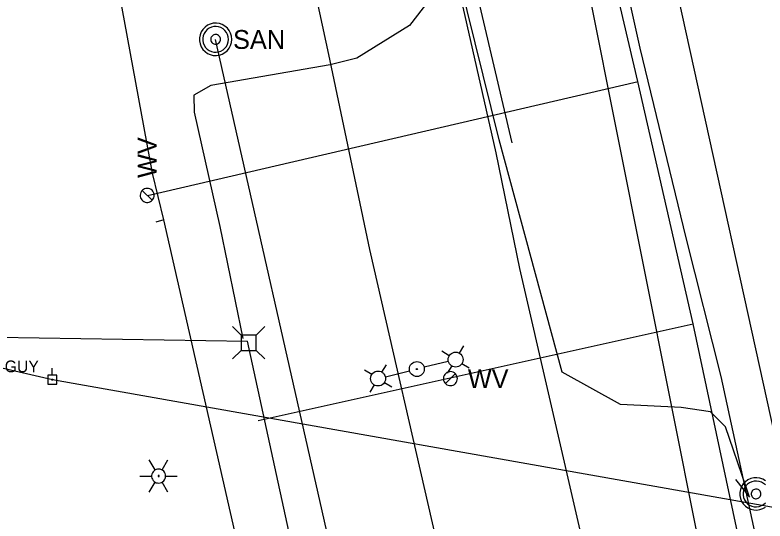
# Model space of a CAD drawing. Extents: x 596028 to 606371, y 330010 to 403088.
# Drawn here: x 604712 to 604864.8, y 339167.3 to 339270.5 of the extents above; entities that cross this region are included whole.
import ezdxf

# ---------------------------------------------------------------- set-up
doc = ezdxf.new("R2010")
doc.units = 0
for name, color, linetype in [('E_LTG', 7, 'Continuous'), ('E_UTL_E_UG', 7, 'Continuous'), ('E_UTL_EGuyWire', 7, 'Continuous'), ('E_UTL_EPowerPole', 7, 'Continuous'), ('E_UTL_FO_UG', 7, 'Continuous'), ('E_UTL_G_UG', 7, 'Continuous'), ('E_UTL_Overhead', 7, 'Continuous'), ('E_UTL_SAN_MH', 7, 'Continuous'), ('E_UTL_SAN_UG', 7, 'Continuous'), ('E_UTL_SAN_UG_MMSD', 7, 'Continuous'), ('E_UTL_T', 7, 'Continuous'), ('E_UTL_T_MH', 7, 'Continuous'), ('E_UTL_T_UG', 7, 'Continuous'), ('E_UTL_W', 7, 'Continuous'), ('E_UTL_W_UG', 7, 'Continuous')]:
    doc.layers.add(name, color=color, linetype=linetype)

# ---------------------------------------------------------------- blocks, each defined once
blk = doc.blocks.new('PPOL')
at = {"layer": 'E_UTL_EPowerPole'}
blk.add_line((-0.2, 13.7), (-0.2, 35.3), dxfattribs=at)
blk.add_lwpolyline([(-13.9, -13.7), (13.5, -13.7), (13.5, 13.7), (-13.9, 13.7)], close=True, dxfattribs=at)
blk.add_circle((0, 0), 1.77, dxfattribs=at)
blk = doc.blocks.new('GUY')
at = {"layer": 'E_UTL_EGuyWire'}
for radius in [12.2, 1.52]:
    blk.add_circle((0, 0), radius, dxfattribs=at)
blk.add_text('GUY', height=36.58, dxfattribs=at).set_placement((30.5, -18.3))

msp = doc.modelspace()

# ---------------------------------------------------------------- linework, layer by layer
at = {"layer": 'E_LTG'}
for p, q in [((604800.51, 339200.96), (604799.01, 339201.87)), ((604802.58, 339201.47), (604803.5, 339202.97)), ((604786.79, 339197.61), (604787.71, 339199.12)), ((604800.29, 339199.81), (604795.41, 339198.62)), ((604801.02, 339198.89), (604800.1, 339197.38)), ((604803.09, 339199.39), (604804.59, 339198.48)), ((604784.72, 339197.11), (604783.22, 339198.02)), ((604787.51, 339196.69), (604792.4, 339197.88)), ((604785.23, 339195.03), (604784.31, 339193.53)), ((604787.3, 339195.54), (604788.8, 339194.63))]:
    msp.add_line(p, q, dxfattribs=at)
for points in [[(604740.57, 339177.67), (604739.38, 339179.73)], [(604742, 339177.67), (604743.19, 339179.73)], [(604742.71, 339176.43), (604742.69, 339176.7), (604742.61, 339176.97), (604742.49, 339177.21), (604742.32, 339177.42), (604742.11, 339177.6), (604741.88, 339177.73), (604741.62, 339177.82), (604741.35, 339177.86), (604741.08, 339177.85), (604740.82, 339177.78), (604740.57, 339177.67), (604740.35, 339177.51), (604740.16, 339177.32), (604740.01, 339177.09), (604739.91, 339176.84), (604739.86, 339176.57), (604739.86, 339176.3), (604739.91, 339176.03), (604740.01, 339175.78), (604740.16, 339175.55), (604740.35, 339175.35), (604740.57, 339175.2), (604740.82, 339175.08), (604741.08, 339175.02), (604741.35, 339175.01), (604741.62, 339175.05), (604741.88, 339175.13), (604742.11, 339175.27), (604742.32, 339175.45), (604742.49, 339175.66), (604742.61, 339175.9), (604742.69, 339176.16), (604742.71, 339176.43)], [(604742.71, 339176.43), (604742.69, 339176.7), (604742.61, 339176.97), (604742.49, 339177.21), (604742.32, 339177.42), (604742.11, 339177.6), (604741.88, 339177.73), (604741.62, 339177.82), (604741.35, 339177.86), (604741.08, 339177.85), (604740.82, 339177.78), (604740.57, 339177.67), (604740.35, 339177.51), (604740.16, 339177.32), (604740.01, 339177.09), (604739.91, 339176.84), (604739.86, 339176.57), (604739.86, 339176.3), (604739.91, 339176.03), (604740.01, 339175.78), (604740.16, 339175.55), (604740.35, 339175.35), (604740.57, 339175.2), (604740.82, 339175.08), (604741.08, 339175.02), (604741.35, 339175.01), (604741.62, 339175.05), (604741.88, 339175.13), (604742.11, 339175.27), (604742.32, 339175.45), (604742.49, 339175.66), (604742.61, 339175.9), (604742.69, 339176.16), (604742.71, 339176.43)], [(604742.71, 339176.43), (604742.69, 339176.7), (604742.61, 339176.97), (604742.49, 339177.21), (604742.32, 339177.42), (604742.11, 339177.6), (604741.88, 339177.73), (604741.62, 339177.82), (604741.35, 339177.86), (604741.08, 339177.85), (604740.82, 339177.78), (604740.57, 339177.67), (604740.35, 339177.51), (604740.16, 339177.32), (604740.01, 339177.09), (604739.91, 339176.84), (604739.86, 339176.57), (604739.86, 339176.3), (604739.91, 339176.03), (604740.01, 339175.78), (604740.16, 339175.55), (604740.35, 339175.35), (604740.57, 339175.2), (604740.82, 339175.08), (604741.08, 339175.02), (604741.35, 339175.01), (604741.62, 339175.05), (604741.88, 339175.13), (604742.11, 339175.27), (604742.32, 339175.45), (604742.49, 339175.66), (604742.61, 339175.9), (604742.69, 339176.16), (604742.71, 339176.43)], [(604737.47, 339176.43), (604739.86, 339176.43)], [(604741.4, 339176.43), (604741.4, 339176.46), (604741.39, 339176.48), (604741.38, 339176.5), (604741.37, 339176.52), (604741.35, 339176.53), (604741.33, 339176.54), (604741.31, 339176.55), (604741.29, 339176.55), (604741.27, 339176.55), (604741.25, 339176.55), (604741.22, 339176.54), (604741.21, 339176.52), (604741.19, 339176.51), (604741.18, 339176.49), (604741.17, 339176.47), (604741.17, 339176.45), (604741.17, 339176.42), (604741.17, 339176.4), (604741.18, 339176.38), (604741.19, 339176.36), (604741.21, 339176.34), (604741.22, 339176.33), (604741.25, 339176.32), (604741.27, 339176.32), (604741.29, 339176.32), (604741.31, 339176.32), (604741.33, 339176.33), (604741.35, 339176.34), (604741.37, 339176.35), (604741.38, 339176.37), (604741.39, 339176.39), (604741.4, 339176.41), (604741.4, 339176.43)], [(604742.71, 339176.43), (604745.09, 339176.43)], [(604739.38, 339173.13), (604740.57, 339175.2)], [(604743.19, 339173.13), (604742, 339175.2)]]:
    msp.add_lwpolyline(points, dxfattribs=at)
for centre, radius in [((604801.8, 339200.18), 1.52), ((604793.9, 339198.25), 1.52), ((604786.01, 339196.32), 1.52), ((604793.9, 339198.25), 0.117)]:
    msp.add_circle(centre, radius, dxfattribs=at)
at = {"layer": 'E_UTL_E_UG'}
msp.add_line((604875.51, 338824.32), (604784.34, 339222.62), dxfattribs=at)
msp.add_lwpolyline([(604784.34, 339222.62), (604775.95, 339262.38), (604768.41, 339297.38), (604762.12, 339328.3), (604755.94, 339361.93), (604755.64, 339363.5), (604751.45, 339378.59), (604743.59, 339418.09), (604735.46, 339449.75), (604728.77, 339482.52), (604722.85, 339509.42)], dxfattribs=at)
at = {"layer": 'E_UTL_EGuyWire'}
msp.add_line((604707.93, 339198.79), (604719.64, 339196.1), dxfattribs=at)
at = {"layer": 'E_UTL_FO_UG'}
msp.add_lwpolyline([(604858.79, 339175.74), (604861.69, 339172.1)], dxfattribs=at)
at = {"layer": 'E_UTL_G_UG'}
for p, q in [((604843.56, 338783.61), (604742.35, 339228.68)), ((604914.69, 338786.08), (604814.85, 339218.78))]:
    msp.add_line(p, q, dxfattribs=at)
for points in [[(604814.85, 339218.78), (604810.09, 339242.37), (604799.43, 339289.54), (604793.26, 339314.06), (604787.02, 339344.67), (604774.66, 339399.62), (604767.29, 339432.61), (604758.85, 339472.19), (604751.42, 339503.86)], [(604742.35, 339228.68), (604740.05, 339238.17), (604732.17, 339281.15), (604723.13, 339319.31), (604718.15, 339342.27), (604709.95, 339377.23), (604705.89, 339396.14), (604699.95, 339418.23), (604694.75, 339444.39), (604689.12, 339468.85), (604685.03, 339486.7), (604684.68, 339487.29), (604678.37, 339490.44), (604676.2, 339500.02)], [(604848.74, 339224.99), (604839.38, 339263.68), (604833.64, 339289.73), (604829.38, 339309.27), (604842.98, 339310.1), (604884.47, 339308.8), (604885.27, 339308.62), (604944.46, 339308.43), (604976.87, 339308.43), (605026.37, 339307.52), (605035.2, 339307.44)], [(604742.35, 339228.68), (604740.7, 339228.23)], [(604930.39, 338852.74), (604855.87, 339196.73), (604848.74, 339224.99)]]:
    msp.add_lwpolyline(points, dxfattribs=at)
at = {"layer": 'E_UTL_Overhead'}
for p, q in [((604870.18, 339169.38), (604841.61, 339299.51)), ((604719.64, 339196.1), (604871.21, 339169.26))]:
    msp.add_line(p, q, dxfattribs=at)
at = {"layer": 'E_UTL_SAN_MH'}
for points in [[(604756.2, 339265.49), (604756.14, 339266.11), (604755.96, 339266.72), (604755.67, 339267.27), (604755.29, 339267.77), (604754.81, 339268.18), (604754.27, 339268.49), (604753.68, 339268.7), (604753.05, 339268.79), (604752.43, 339268.76), (604751.82, 339268.61), (604751.25, 339268.35), (604750.74, 339267.98), (604750.3, 339267.53), (604749.96, 339267), (604749.73, 339266.42), (604749.61, 339265.8), (604749.61, 339265.18), (604749.73, 339264.56), (604749.96, 339263.98), (604750.3, 339263.45), (604750.74, 339262.99), (604751.25, 339262.63), (604751.82, 339262.37), (604752.43, 339262.22), (604753.05, 339262.19), (604753.68, 339262.28), (604754.27, 339262.49), (604754.81, 339262.8), (604755.29, 339263.21), (604755.67, 339263.7), (604755.96, 339264.26), (604756.14, 339264.86), (604756.2, 339265.49)], [(604756.2, 339265.49), (604756.14, 339266.11), (604755.96, 339266.72), (604755.67, 339267.27), (604755.29, 339267.77), (604754.81, 339268.18), (604754.27, 339268.49), (604753.68, 339268.7), (604753.05, 339268.79), (604752.43, 339268.76), (604751.82, 339268.61), (604751.25, 339268.35), (604750.74, 339267.98), (604750.3, 339267.53), (604749.96, 339267), (604749.73, 339266.42), (604749.61, 339265.8), (604749.61, 339265.18), (604749.73, 339264.56), (604749.96, 339263.98), (604750.3, 339263.45), (604750.74, 339262.99), (604751.25, 339262.63), (604751.82, 339262.37), (604752.43, 339262.22), (604753.05, 339262.19), (604753.68, 339262.28), (604754.27, 339262.49), (604754.81, 339262.8), (604755.29, 339263.21), (604755.67, 339263.7), (604755.96, 339264.26), (604756.14, 339264.86), (604756.2, 339265.49)], [(604755.54, 339265.49), (604755.49, 339265.99), (604755.35, 339266.47), (604755.12, 339266.92), (604754.81, 339267.31), (604754.43, 339267.64), (604753.99, 339267.89), (604753.52, 339268.05), (604753.02, 339268.13), (604752.52, 339268.1), (604752.03, 339267.98), (604751.58, 339267.78), (604751.17, 339267.48), (604750.82, 339267.12), (604750.55, 339266.7), (604750.36, 339266.23), (604750.27, 339265.74), (604750.27, 339265.24), (604750.36, 339264.75), (604750.55, 339264.28), (604750.82, 339263.86), (604751.17, 339263.49), (604751.58, 339263.2), (604752.03, 339262.99), (604752.52, 339262.88), (604753.02, 339262.85), (604753.52, 339262.92), (604753.99, 339263.09), (604754.43, 339263.34), (604754.81, 339263.67), (604755.12, 339264.06), (604755.35, 339264.51), (604755.49, 339264.99), (604755.54, 339265.49)], [(604755.54, 339265.49), (604755.49, 339265.99), (604755.35, 339266.47), (604755.12, 339266.92), (604754.81, 339267.31), (604754.43, 339267.64), (604753.99, 339267.89), (604753.52, 339268.05), (604753.02, 339268.13), (604752.52, 339268.1), (604752.03, 339267.98), (604751.58, 339267.78), (604751.17, 339267.48), (604750.82, 339267.12), (604750.55, 339266.7), (604750.36, 339266.23), (604750.27, 339265.74), (604750.27, 339265.24), (604750.36, 339264.75), (604750.55, 339264.28), (604750.82, 339263.86), (604751.17, 339263.49), (604751.58, 339263.2), (604752.03, 339262.99), (604752.52, 339262.88), (604753.02, 339262.85), (604753.52, 339262.92), (604753.99, 339263.09), (604754.43, 339263.34), (604754.81, 339263.67), (604755.12, 339264.06), (604755.35, 339264.51), (604755.49, 339264.99), (604755.54, 339265.49)], [(604753.89, 339265.49), (604753.87, 339265.68), (604753.82, 339265.86), (604753.73, 339266.02), (604753.61, 339266.17), (604753.47, 339266.3), (604753.31, 339266.39), (604753.13, 339266.45), (604752.94, 339266.48), (604752.76, 339266.47), (604752.57, 339266.42), (604752.4, 339266.35), (604752.25, 339266.24), (604752.12, 339266.1), (604752.02, 339265.94), (604751.95, 339265.77), (604751.91, 339265.58), (604751.91, 339265.39), (604751.95, 339265.21), (604752.02, 339265.04), (604752.12, 339264.88), (604752.25, 339264.74), (604752.4, 339264.63), (604752.57, 339264.55), (604752.76, 339264.51), (604752.94, 339264.5), (604753.13, 339264.53), (604753.31, 339264.59), (604753.47, 339264.68), (604753.61, 339264.81), (604753.73, 339264.95), (604753.82, 339265.12), (604753.87, 339265.3), (604753.89, 339265.49)], [(604753.89, 339265.49), (604753.87, 339265.68), (604753.82, 339265.86), (604753.73, 339266.02), (604753.61, 339266.17), (604753.47, 339266.3), (604753.31, 339266.39), (604753.13, 339266.45), (604752.94, 339266.48), (604752.76, 339266.47), (604752.57, 339266.42), (604752.4, 339266.35), (604752.25, 339266.24), (604752.12, 339266.1), (604752.02, 339265.94), (604751.95, 339265.77), (604751.91, 339265.58), (604751.91, 339265.39), (604751.95, 339265.21), (604752.02, 339265.04), (604752.12, 339264.88), (604752.25, 339264.74), (604752.4, 339264.63), (604752.57, 339264.55), (604752.76, 339264.51), (604752.94, 339264.5), (604753.13, 339264.53), (604753.31, 339264.59), (604753.47, 339264.68), (604753.61, 339264.81), (604753.73, 339264.95), (604753.82, 339265.12), (604753.87, 339265.3), (604753.89, 339265.49)]]:
    msp.add_lwpolyline(points, dxfattribs=at)
at = {"layer": 'E_UTL_SAN_UG'}
msp.add_line((604802.36, 339046.2), (604752.9, 339265.49), dxfattribs=at)
at = {"layer": 'E_UTL_SAN_UG_MMSD'}
msp.add_line((604854.51, 339147.21), (604642.2, 340212.1), dxfattribs=at)
at = {"layer": 'E_UTL_T'}
for points in [[(604758.08, 339205.16), (604756.33, 339206.91)], [(604761.18, 339205.16), (604762.93, 339206.91)], [(604761.18, 339205.16), (604758.08, 339205.16)], [(604758.08, 339205.16), (604758.08, 339202.06)], [(604761.18, 339202.06), (604761.18, 339205.16)], [(604758.08, 339202.06), (604756.33, 339200.31)], [(604758.08, 339202.06), (604761.18, 339202.06)], [(604761.18, 339202.06), (604762.93, 339200.31)]]:
    msp.add_lwpolyline(points, dxfattribs=at)
at = {"layer": 'E_UTL_T_MH'}
for points in [[(604864.92, 339175.48), (604864.38, 339175.79), (604863.78, 339175.99), (604863.16, 339176.08), (604862.54, 339176.05), (604861.93, 339175.91), (604861.36, 339175.64), (604860.84, 339175.28), (604860.41, 339174.83), (604860.07, 339174.3), (604859.84, 339173.72), (604859.72, 339173.1), (604859.72, 339172.47), (604859.84, 339171.86), (604860.07, 339171.27), (604860.41, 339170.75), (604860.84, 339170.29), (604861.36, 339169.93), (604861.93, 339169.67), (604862.54, 339169.52), (604863.16, 339169.49), (604863.78, 339169.58), (604864.38, 339169.79), (604864.92, 339170.1)], [(604864.92, 339174.61), (604864.54, 339174.94), (604864.1, 339175.19), (604863.63, 339175.35), (604863.13, 339175.42), (604862.63, 339175.4), (604862.14, 339175.28), (604861.69, 339175.07), (604861.28, 339174.78), (604860.93, 339174.42), (604860.66, 339174), (604860.47, 339173.53), (604860.38, 339173.04), (604860.38, 339172.54), (604860.47, 339172.04), (604860.66, 339171.58), (604860.93, 339171.16), (604861.28, 339170.79), (604861.69, 339170.5), (604862.14, 339170.29), (604862.63, 339170.17), (604863.13, 339170.15), (604863.63, 339170.22), (604864.1, 339170.39), (604864.54, 339170.64), (604864.92, 339170.97)], [(604864, 339172.79), (604863.98, 339172.97), (604863.93, 339173.15), (604863.84, 339173.32), (604863.72, 339173.47), (604863.58, 339173.59), (604863.42, 339173.69), (604863.24, 339173.75), (604863.05, 339173.78), (604862.87, 339173.77), (604862.68, 339173.72), (604862.51, 339173.64), (604862.36, 339173.54), (604862.23, 339173.4), (604862.13, 339173.24), (604862.06, 339173.07), (604862.02, 339172.88), (604862.02, 339172.69), (604862.06, 339172.51), (604862.13, 339172.33), (604862.23, 339172.18), (604862.36, 339172.04), (604862.51, 339171.93), (604862.68, 339171.85), (604862.87, 339171.81), (604863.05, 339171.8), (604863.24, 339171.82), (604863.42, 339171.89), (604863.58, 339171.98), (604863.72, 339172.1), (604863.84, 339172.25), (604863.93, 339172.42), (604863.98, 339172.6), (604864, 339172.79)]]:
    msp.add_lwpolyline(points, dxfattribs=at)
at = {"layer": 'E_UTL_T_UG'}
for p in [(604596.67, 339206.62), (604851.26, 338782.4)]:
    msp.add_line(p, (604759.41, 339203.92), dxfattribs=at)
for points in [[(604575.94, 339307.43), (604597.53, 339325.48), (604613.47, 339330.97), (604642.43, 339330.6), (604667.83, 339327.05), (604687.13, 339326.8), (604711.31, 339326.64), (604738.96, 339324.52), (604751.88, 339325.58), (604773.02, 339324.69), (604805.62, 339276.9), (604813.27, 339244.39)], [(604801.08, 339284.89), (604800.73, 339279.22), (604792.4, 339268.31), (604781.64, 339261.64), (604776.22, 339260.28), (604751.92, 339256.11), (604748.44, 339254.09), (604748.54, 339250.65), (604753.73, 339227.31), (604758.47, 339204.5)], [(604861.66, 339172.14), (604860.9, 339174.37), (604856.77, 339186.5), (604853.76, 339189.54), (604847.78, 339190.4), (604835.42, 339191.04), (604823.52, 339197.63), (604810.64, 339244.98), (604804.14, 339271.36), (604801.08, 339284.89)]]:
    msp.add_lwpolyline(points, dxfattribs=at)
at = {"layer": 'E_UTL_W'}
for points in [[(604738.97, 339235.1), (604738.7, 339235.07), (604738.44, 339234.99), (604738.2, 339234.87), (604737.98, 339234.7), (604737.81, 339234.5), (604737.67, 339234.26), (604737.58, 339234.01), (604737.54, 339233.74), (604737.56, 339233.47), (604737.62, 339233.2), (604737.73, 339232.96), (604737.89, 339232.74), (604738.09, 339232.55), (604738.31, 339232.4), (604738.57, 339232.3), (604738.83, 339232.25), (604739.1, 339232.25), (604739.37, 339232.3), (604739.62, 339232.4), (604739.85, 339232.55), (604740.05, 339232.74), (604740.2, 339232.96), (604740.32, 339233.2), (604740.38, 339233.47), (604740.39, 339233.74), (604740.35, 339234.01), (604740.26, 339234.26), (604740.13, 339234.5), (604739.95, 339234.7), (604739.74, 339234.87), (604739.5, 339234.99), (604739.24, 339235.07), (604738.97, 339235.1)], [(604739.98, 339232.66), (604737.96, 339234.68)], [(604802.15, 339196.29), (604802.12, 339196.56), (604802.04, 339196.82), (604801.92, 339197.06), (604801.75, 339197.28), (604801.55, 339197.45), (604801.31, 339197.59), (604801.06, 339197.68), (604800.79, 339197.72), (604800.52, 339197.7), (604800.25, 339197.64), (604800.01, 339197.53), (604799.79, 339197.37), (604799.6, 339197.17), (604799.45, 339196.95), (604799.35, 339196.69), (604799.3, 339196.43), (604799.3, 339196.16), (604799.35, 339195.89), (604799.45, 339195.64), (604799.6, 339195.41), (604799.79, 339195.21), (604800.01, 339195.06), (604800.25, 339194.94), (604800.52, 339194.88), (604800.79, 339194.87), (604801.06, 339194.91), (604801.31, 339194.99), (604801.55, 339195.13), (604801.75, 339195.31), (604801.92, 339195.52), (604802.04, 339195.76), (604802.12, 339196.02), (604802.15, 339196.29)], [(604799.71, 339195.28), (604801.73, 339197.3)]]:
    msp.add_lwpolyline(points, dxfattribs=at)
at = {"layer": 'E_UTL_W_UG'}
for p, q in [((604739.01, 339233.67), (604838.98, 339256.92)), ((604761.59, 339187.79), (604850.17, 339207.5))]:
    msp.add_line(p, q, dxfattribs=at)
msp.add_lwpolyline([(604874.71, 339088.99), (604861.04, 339156.34), (604850.17, 339207.5), (604838.95, 339256.89), (604821.49, 339331.51)], dxfattribs=at)

# ---------------------------------------------------------------- block references
at = {"layer": 'E_UTL_EGuyWire', "xscale": 0.06561666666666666, "yscale": 0.06561666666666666}
msp.add_blockref('GUY', (604707.93, 339198.79), dxfattribs=at)
at = {"layer": 'E_UTL_EPowerPole', "xscale": 0.06561666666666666, "yscale": 0.06561666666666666}
msp.add_blockref('PPOL', (604719.64, 339196.1), dxfattribs=at)

# ---------------------------------------------------------------- texts
at = {"layer": 'E_UTL_SAN_MH'}
msp.add_text('SAN', height=3.849, dxfattribs=at).set_placement((604756.46, 339263.54))
msp.add_text('SAN', height=3.849, dxfattribs=at).set_placement((604756.46, 339263.54))
at = {"layer": 'E_UTL_W'}
msp.add_text('WV', height=3.85, rotation=90, dxfattribs=at).set_placement((604740.89, 339237.23))
msp.add_text('WV', height=3.85, dxfattribs=at).set_placement((604804.29, 339194.37))

doc.saveas('drawing.dxf')
